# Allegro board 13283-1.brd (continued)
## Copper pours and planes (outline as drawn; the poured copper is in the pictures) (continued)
TPS51216_PHS_SET on BOTTOM: 93.72,18.41 93.85,18.53 94.33,18.53 94.41,18.46 94.41,17.59 94.54,17.47 95.17,17.47 95.27,17.37 95.27,15.79 95.22,15.74 93.77,15.74 93.72,15.79
USB20_VCCA on TOP: 15.97,40.65 15.97,43.04 14.09,44.92 12.01,44.92 11.47,45.47 11.47,46.61 11.61,46.75 16.58,46.75 18.01,45.33 18.01,44.72 18.26,44.47 18.44,44.47 18.64,44.26 18.64,42.69 18.67,42.69 18.87,42.49 20.44,42.49 20.6,42.33 22.07,42.33 28.06,36.34 30.1,36.34 31.93,34.51 31.93,33.29 25.27,33.29 24.92,33.65 24.92,35.63 20.8,39.74 16.88,39.74
USB20_VCCB on TOP: 181.61,4.17 181.48,4.3 181.48,5.45 182.88,5.45 182.88,5.86 182.85,5.88 181.46,5.88 181.46,6.43 181.48,6.46 182.9,6.46 182.9,6.85 181.48,6.85 181.48,7.45 182.91,7.45 182.91,7.85 182.5,7.85 182.5,7.85 181.48,7.85 181.48,8.45 186.19,8.45 186.96,7.68 186.96,4.51 186.62,4.17
USB20_VCCB on BOTTOM: 157.7,8.58 166.44,8.58 167.45,9.58 169.51,9.58 172.36,12.44 181.65,12.44 183.21,10.88 183.21,9.97 185.11,8.07 185.24,8.07 185.25,8.08 186.01,8.08 186.95,7.13 186.95,5.56 186.91,5.52 182.71,5.52 180.67,7.56 180.67,9.24 180.17,9.74 173.5,9.74 170.76,7 170.76,6.93 170.63,6.8 170.63,5.91 169.85,5.12 159.05,5.12 158.57,4.64 158.57,3.37 157.25,2.05 150.14,2.05 149.93,2.25 149.93,4.03 150.24,4.34 151.61,4.34 152.37,5.1 154.22,5.1 ; 5 cut-outs
USB30_VCCC on TOP: 14.87,27.42 14.57,27.72 14.57,28.26 14.47,28.37 14.47,30.29 14.86,30.68 19.2,30.68 19.2,30.68 23.29,30.68 23.92,31.31 31.42,31.31 31.87,30.85 31.87,29.63 30.1,29.63 29.54,29.07 24.08,29.07 22.43,27.42 ; 7 cut-outs
VGA_CORE on TOP: 168.22,113.35 167.08,114.5 166.57,114.5 166.19,114.11 165.94,114.11 165.55,114.5 162.63,114.5 162,115.13 161.36,115.13 161.24,115.26 161.24,115.64 161.36,115.77 161.87,115.77 162,115.89 162,116.53 162.13,116.65 162.38,116.65 162.51,116.53 162.51,115.89 162.63,115.77 163.27,115.77 163.4,115.89 163.4,119.7 163.27,119.83 163.01,119.83 162.89,119.96 162.89,120.21 163.01,120.34 164.41,120.34 164.67,120.08 164.67,119.58 164.79,119.45 165.05,119.45 165.3,119.19 165.3,118.81 165.17,118.69 164.79,118.69 164.67,118.56 164.67,118.05 165.3,117.42 165.3,117.04 165.17,116.91 165.05,116.91 164.67,116.53 164.67,116.27 165.81,115.13 166.19,115.13 166.44,115.38 166.44,121.1 166.57,121.23 167.08,121.23 167.59,120.72 168.09,120.72 168.22,120.85 168.22,121.73 168.35,121.86 168.86,121.86 168.98,121.73 168.98,113.48 168.86,113.35 ; 22 cut-outs
VGA_CORE on TOP: 177.77,87.29 173.94,91.13 173.94,95.32 172.67,96.59 172.67,97.86 172.92,98.11 174.32,98.11 174.44,98.24 179.47,98.24 180.92,96.79 180.92,87.7 180.52,87.29 ; 4 cut-outs
VGA_CORE on BOTTOM: 174.32,90.75 173.94,91.13 173.94,95.19 173.56,95.57 173.56,97.99 173.68,98.11 177.11,98.11 177.24,98.24 179.02,98.24 179.27,98.49 182.95,98.49 183.08,98.37 183.08,97.25 182.7,96.87 182.7,84.4 181.89,83.58 176.91,83.58 174.32,86.17 ; 10 cut-outs
VGA_CORE on BOTTOM: outline of 89 points within 161.43,113.57 169.74,121.38
VGA_CORE on L2VCC: 174.4,87 174.38,87.02 174.38,90.19 174,90.57 174,93.87 161.81,106.19 161.81,121.04 165.09,121.04 165.35,120.78 166.65,120.78 167.16,121.29 169.43,121.29 169.43,112.77 181.62,100.57 181.62,87.14 181.48,87
VGA_CORE on L3: 170.51,121.23 171.65,120.08 171.65,114.24 182.45,103.45 182.45,88.08 181.56,87.19 174.83,87.19 173.94,88.08 173.94,92.27 161.49,104.72 161.49,120.72 161.74,120.97 165.05,120.97 165.3,120.72 166.57,120.72 167.08,121.23

Small or netless copper shapes (teardrops, artwork), in the pictures only: 1 on TOP, 3 on BOTTOM, 2 on L3

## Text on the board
Ref Des/Silkscreen Bottom: X601:32.768KHZ | X1902:48MHZ | F5401:1.1A/6V | X3001:25MHZ | X7503:27MHZ | REV:A00 | Cedar AMD MB | 13283-1 | MADE IN TAIWAN | PWB:XY1KC
Ref Des/Silkscreen Top: F5201:1.1A/24V | F5203:1.1A/24V | F6201:0.5A/6V
User.27: AUD_AGND | GND
User.28: AUD_AGND | APU_VDD | 1D35V_S3 | APU_VDDNB | 0D95V_S0 | GND | DCBATOUT | VGA_CORE | 1D35V_VGA_S0
User.32: ByImpedance:100.0@_REF_L1=("4.0/6.0(L1)" "5.0/11.0(L1)")|_REF_L6=("4.0/6.0(L6)" "5.0/11.0(L6)")|Type="DP"|_REF_L4=("4.0/9.0(L4)")|_REF_L3=("4.0/9.0(L3)")|imp="100.0" | ByImpedance:110.0@_REF_L1=("4.0/12.0(L1)")|_REF_L6=("4.0/12.0(L6)")|Type="DP"|_REF_L4=("3.5/13.0(L4)")|_REF_L3=("3.5/13.0(L3)")|imp="110.0" | ByImpedance:27.4@_REF_L1=("16.0(L1)")|_REF_L6=("16.0(L6)")|Type="SE"|_REF_L4=("16.0(L4)")|_REF_L3=("16.0(L3)")|imp="27.4" | ByImpedance:33.0@_REF_L1=("12.0(L1)")|_REF_L6=("12.0(L6)")|Type="SE"|_REF_L4=("12.0(L4)")|_REF_L3=("12.0(L3)")|imp="33.0" | ByImpedance:35.0@_REF_L1=("11.0(L1)")|_REF_L6=("11.0(L6)")|Type="SE"|_REF_L4=("10.5(L4)")|_REF_L3=("10.5(L3)")|imp="35.0" | ByImpedance:37.5@_REF_L1=("10.0(L1)")|_REF_L6=("10.0(L6)")|Type="SE"|_REF_L4=("9.5(L4)")|_REF_L3=("9.5(L3)")|imp="37.5" | ByImpedance:40.0@_REF_L1=("8.5(L1)")|_REF_L6=("8.5(L6)")|Type="SE"|_REF_L4=("8.5(L4)")|_REF_L3=("8.5(L3)")|imp="40.0" | ByImpedance:45.0@_REF_L1=("7.0(L1)")|_REF_L6=("7.0(L6)")|Type="SE"|_REF_L4=("6.5(L4)")|_REF_L3=("6.5(L3)")|imp="45.0" | ByImpedance:48.0@_REF_L1=("6.0(L1)")|_REF_L6=("6.0(L6)")|Type="SE"|_REF_L4=("5.5(L4)")|_REF_L3=("5.5(L3)")|imp="48.0" | ByImpedance:50.0@_REF_L1=("5.5(L1)")|_REF_L6=("5.5(L6)")|Type="SE"|_REF_L4=("5.0(L4)")|_REF_L3=("5.0(L3)")|imp="50.0" | ByImpedance:52.0@_REF_L1=("5.0(L1)")|_REF_L6=("5.0(L6)")|Type="SE"|_REF_L4=("4.5(L4)")|_REF_L3=("4.5(L3)")|imp="52.0" | ByImpedance:55.0@_REF_L1=("4.5(L1)")|_REF_L6=("4.5(L6)")|Type="SE"|_REF_L4=("4.0(L4)")|_REF_L3=("4.0(L3)")|imp="55.0" | ByImpedance:60.0@_REF_L1=("3.5(L1)")|_REF_L6=("3.5(L6)")|Type="SE"|_REF_L4=("nil(L4)")|_REF_L3=("nil(L3)")|imp="60.0" | ByImpedance:65.0@_REF_L1=("10.0/5.0(L1)")|_REF_L6=("10.0/5.0(L6)")|Type="DP"|_REF_L4=("9.0/5.0(L4)")|_REF_L3=("9.0/5.0(L3)")|imp="65.0" | ByImpedance:70.0@_REF_L1=("8.5/5.0(L1)")|_REF_L6=("8.5/5.0(L6)")|Type="DP"|_REF_L4=("8.0/6.0(L4)")|_REF_L3=("8.0/6.0(L3)")|imp="70.0" | ByImpedance:72.0@_REF_L1=("8.0/5.0(L1)")|_REF_L6=("8.0/5.0(L6)")|Type="DP"|_REF_L4=("7.0/5.0(L4)")|_REF_L3=("7.0/5.0(L3)")|imp="72.0" | ByImpedance:75.0@_REF_L1=("7.0/4.5(L1)")|_REF_L6=("7.0/4.5(L6)")|Type="DP"|_REF_L4=("7.0/6.0(L4)")|_REF_L3=("7.0/6.0(L3)")|imp="75.0" | ByImpedance:80.0@_REF_L1=("5.5/4.0(L1)" "6.0/4.5(L1)")|_REF_L6=("5.5/4.0(L6)" "6.0/4.5(L6)")|Type="DP"|_REF_L4=("6.0/6.0(L4)" "5.0/4.0(L4)")|_REF_L3=("6.0/6.0(L3)" "5.0/4.0(L3)")|imp="80.0" | ByImpedance:85.0@_REF_L1=("5.0/4.5(L1)" "6.0/6.0(L1)")|_REF_L6=("5.0/4.5(L6)" "6.0/6.0(L6)")|Type="DP"|_REF_L4=("5.0/5.5(L4)" "4.5/4.5(L4)")|_REF_L3=("5.0/5.5(L3)" "4.5/4.5(L3)")|imp="85.0" | ByImpedance:90.0@_REF_L1=("4.0/4.0(L1)" "5.5/7.0(L1)" "5.0/6.0(L1)")|_REF_L6=("4.0/4.0(L6)" "5.5/7.0(L6)" "5.0/6.0(L6)")|Type="DP"|_REF_L4=("5.0/8.0(L4)" "4.0/5.0(L4)" "5.5/10.0(L4)")|_REF_L3=("5.0/8.0(L3)" "4.0/5.0(L3)" "5.5/10.0(L3)")|imp="90.0" | ByImpedance:93.0@_REF_L1=("4.0/4.5(L1)" "5.0/6.5(L1)")|_REF_L6=("4.0/4.5(L6)" "5.0/6.5(L6)")|Type="DP"|_REF_L4=("5.0/9.0(L4)" "4.0/5.5(L4)")|_REF_L3=("5.0/9.0(L3)" "4.0/5.5(L3)")|imp="93.0" | ByImpedance:95.0@_REF_L1=("4.5/6.0(L1)")|_REF_L6=("4.5/6.0(L6)")|Type="DP"|_REF_L4=("4.0/6.5(L4)")|_REF_L3=("4.0/6.5(L3)")|imp="95.0" | LayerIndex:nil | Source:6-1.3-4c.xls | artWorks:("_REF_L3" "_REF_L4" "_REF_L6" "_REF_L1") | gtImpOutlineUsed:BOARD GEOMETRY/PANEL_OUTLINE
User.33: Board Accuracy Check,Mar 06 15:21:11 2014,Passed | Dummy-Static-No Shape On Layer Check,Mar 06 15:21:12 2014,Passed | Split Plane Check,Feb 10 12:07:49 2014,Passed
User.36: This gerber is just for your reference to find the DP impedance traces in layer L1. | DP IMPEDANCE TABLE: L1 | * - Denotes that WIDTH | is NOT used in this layer | inside board outline. | IMP(Ohm) | 65.0 | 70.0 | 72.0 | 75.0 | 80.0 | 85.0 | 90.0 | 93.0 | 95.0 | 100.0 | 110.0 | WIDTH(mils) | 10.0/5.0 | *8.5/5.0 | *8.0/5.0 | *7.0/4.5 | *5.5/4.0 | *6.0/4.5 | 5.0/4.5 | *6.0/6.0 | 4.0/4.0 | *5.5/7.0 | *5.0/6.0 | *4.0/4.5 | *5.0/6.5 | *4.5/6.0 | 4.0/6.0 | *5.0/11.0 | *4.0/12.0 | TYPE | DP
User.38: This gerber is just for your reference to find the SE impedance traces in layer L1. | SE IMPEDANCE TABLE: L1 | * - Denotes that WIDTH | is NOT used in this layer | inside board outline. | IMP(Ohm) | 27.4 | 33.0 | 35.0 | 37.5 | 40.0 | 45.0 | 48.0 | 50.0 | 52.0 | 55.0 | 60.0 | WIDTH(mils) | 16.0 | 12.0 | 11.0 | 10.0 | *8.5 | 7.0 | *6.0 | 5.5 | 5.0 | 4.5 | *3.5 | TYPE | SE
User.40: This gerber is just for your reference to find the DP impedance traces in layer L3. | DP IMPEDANCE TABLE: L3 | * - Denotes that WIDTH | is NOT used in this layer | inside board outline. | IMP(Ohm) | 65.0 | 70.0 | 72.0 | 75.0 | 80.0 | 85.0 | 90.0 | 93.0 | 95.0 | 100.0 | 110.0 | WIDTH(mils) | *9.0/5.0 | *8.0/6.0 | 7.0/5.0 | *7.0/6.0 | *6.0/6.0 | *5.0/4.0 | *5.0/5.5 | 4.5/4.5 | *5.0/8.0 | 4.0/5.0 | *5.5/10.0 | *5.0/9.0 | *4.0/5.5 | *4.0/6.5 | 4.0/9.0 | *3.5/13.0 | TYPE | DP
User.42: This gerber is just for your reference to find the SE impedance traces in layer L3. | SE IMPEDANCE TABLE: L3 | * - Denotes that WIDTH | is NOT used in this layer | inside board outline. | IMP(Ohm) | 27.4 | 33.0 | 35.0 | 37.5 | 40.0 | 45.0 | 48.0 | 50.0 | 52.0 | 55.0 | 60.0 | WIDTH(mils) | *16.0 | *12.0 | *10.5 | *9.5 | 8.5 | 6.5 | 5.5 | 5.0 | *4.5 | 4.0 | *nil | TYPE | SE
User.44: This gerber is just for your reference to find the DP impedance traces in layer L4. | DP IMPEDANCE TABLE: L4 | * - Denotes that WIDTH | is NOT used in this layer | inside board outline. | IMP(Ohm) | 65.0 | 70.0 | 72.0 | 75.0 | 80.0 | 85.0 | 90.0 | 93.0 | 95.0 | 100.0 | 110.0 | WIDTH(mils) | *9.0/5.0 | *8.0/6.0 | *7.0/5.0 | *7.0/6.0 | *6.0/6.0 | 5.0/4.0 | *5.0/5.5 | 4.5/4.5 | *5.0/8.0 | 4.0/5.0 | *5.5/10.0 | *5.0/9.0 | *4.0/5.5 | *4.0/6.5 | *4.0/9.0 | *3.5/13.0 | TYPE | DP
User.45: Note:Refer to DRILL layer for ELLIPSE drill direction | FIGURE | SIZE | 10.0 | 16.0 | 21.0 | 28.0 | 30.0 | 32.0 | 36.0 | 37.0 | 40.0 | 115.0 | 117.0 | 166.0 | 44.0 | 46.0 | 48.0 | 50.0 | 52.0 | 63.0 | 69.0 | 86.0 | 138.0 | 140.0 | 158.0 | 60.0x24.0 | 71.0x36.0 | 83.0x28.0 | 91.0x36.0 | 95.0x28.0 | 95.0x36.0 | 95.0x40.0 | 98.0x28.0 | 109.0x28.0 | 178.0x138.0 | DRILL CHART: TOP to BOTTOM | ALL UNITS ARE IN MILS | PLATED | NON-PLATED | QTY | 2837 | 699 | 19 | 9 | 28 | 7 | 8 | 4 | 6 | 2 | 3 | 1 | This gerber is just for your reference to find the DP impedance traces in layer L6. | This gerber is just for your reference to find the SE impedance traces in layer L4. | This gerber is just for your reference to find the SE impedance traces in layer L6. | DP IMPEDANCE TABLE: L6 | SE IMPEDANCE TABLE: L4 | SE IMPEDANCE TABLE: L6 | * - Denotes that WIDTH | is NOT used in this layer | inside board outline. | Model | Cedar AMD MB | PCB_NO | 13283 | VER. | Layer | DRILL | L1 | L2VCC | L3 | TMASK | TPLACE | TSILK | TSMD | Designer | CyRiL | Date | 03/06/2014 | IMP(Ohm) | 27.4 | 65.0 | 33.0 | 70.0 | 35.0 | 72.0 | 37.5 | 75.0 | 80.0 | 45.0 | 85.0 | 90.0 | 55.0 | 60.0 | 93.0 | 95.0 | 100.0 | 110.0 | WIDTH(mils) | *16.0 | *12.0 | 12.0 | *11.0 | 10.5 | *9.5 | 8.5 | 6.5 | 7.0 | *6.0 | 5.5 | 5.0 | *4.5 | 4.0 | 4.5 | *3.5 | *nil | 10.0/5.0 | *8.5/5.0 | *8.0/5.0 | *7.0/4.5 | 5.5/4.0 | *6.0/4.5 | 5.0/4.5 | *6.0/6.0 | 4.0/4.0 | *5.5/7.0 | *5.0/6.0 | *4.0/4.5 | *5.0/6.5 | *4.5/6.0 | 4.0/6.0 | *5.0/11.0 | *4.0/12.0 | TYPE | SE | DP | BMASK | BPLACE | BSILK | BSMD | L4 | L5GND | L6
